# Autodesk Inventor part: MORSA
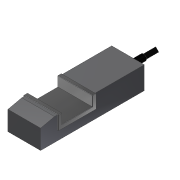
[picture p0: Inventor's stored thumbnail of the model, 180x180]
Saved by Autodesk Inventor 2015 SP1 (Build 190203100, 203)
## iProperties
Created: 2014-10
Part Number: MORSA
Material: Generic
Document SubType Name: Modeling
Designer: Guilherme Augusto
Density: 1 g/cm^3
Appearance: Default
Author: Guilherme Augusto
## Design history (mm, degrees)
sketch "Sketch1"
  geometry: L1 (-49, 32)-(-49, 0); L2 (-49, 0)-(49, 0); L3 (49, 0)-(49, 32); L4 (49, 32)-(61, 32); L5 (61, 32)-(61, -12); L6 (61, -12)-(-61, -12); L7 (-61, -12)-(-61, 32); L8 (-61, 32)-(-49, 32); 2 further points
  constraints: 16 end point, 6 perpendicular, 1 coincident, 1 collinear, 1 horizontal, 1 midpoint, 1 point on line, 1 vertical
  dimensions: "d0" = 12 distance of L1.start L7.end; "d1" = 32 distance of L1.start L1.end; "d2" = 12 distance between parallel lines of L2 L6 (= d0); "d3" = 98 distance between parallel lines of L1 L3
extrude "Extrusion1" new body sketch "Sketch1" stored distance "d4" = 113; taper "d5" = 0 deg
sketch "Sketch2"
  geometry: L1 (-61, -12)-(-61, 32) reference; L2 (61, 32)-(61, -12) reference; L3 (61, -12)-(-61, -12) reference; L4 (-61, 31)-(-71, 31); L5 (-71, 31)-(-116, 21); L6 (-116, 21)-(-116, -42); L7 (-116, -42)-(221, -42); L8 (221, -42)-(221, 31); L9 (221, 31)-(61, 31); L10 (61, -12)-(61, 31); L11 (-61, 31)-(-61, -12); 1 further point
  constraints: 16 end point, 4 perpendicular, 3 point on line, 2 collinear, 1 horizontal
  dimensions: "d9" = 160 distance of L8.end L9.end; "d10" = 55 distance between parallel lines of L6 L1; "d11" = 10 distance of L4.start L4.end; "d12" = 30 distance between parallel lines of L3 L7; "d13" = 10 vertical distance of L4.end L5.end; "d14" = 1 distance from line of L1.end L4
extrude "Extrusion2" join sketch "Sketch2" stored distance "d15" = 106; taper "d16" = 0 deg
sketch "Sketch3"
  geometry: C1 r 10 at (53, 42); 1 further point
  constraints: 1 centre point, 1 coincident
  dimensions: "d17" = 20 diameter of C1
extrude "Extrusion3" join sketch "Sketch3" distance "d18" = 50; taper "d19" = 0 deg
sketch "Sketch4"
  geometry: L1 (0, 10)-(10, 0); L2 (10, 0)-(0, -10); L3 (0, -10)-(-10, 0); L4 (-10, 0)-(0, 10); 2 further points
  constraints: 8 end point, 1 coincident, 1 vertical alignment, 9 other
  dimensions: "d21" = 20 distance of L2.end L1.start
extrude "Extrusion4" join sketch "Sketch4" distance "d22" = 40; taper "d23" = 0 deg
chamfer "Chamfer1" distance "d6" = 1; stored, may be unused: second distance "d7" = 2, angle "d8" = 45 deg
body "Solid1"
